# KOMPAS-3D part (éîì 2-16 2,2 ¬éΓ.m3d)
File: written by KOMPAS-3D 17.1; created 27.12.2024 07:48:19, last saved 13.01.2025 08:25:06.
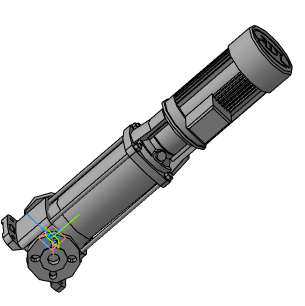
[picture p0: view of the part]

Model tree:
1. Операция без истории:3
2. Эскиз:1
3. Элемент выдавливания:1  (labels: ВМН 2-16 2,2 кВт)
     Расстояние 2 = 250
